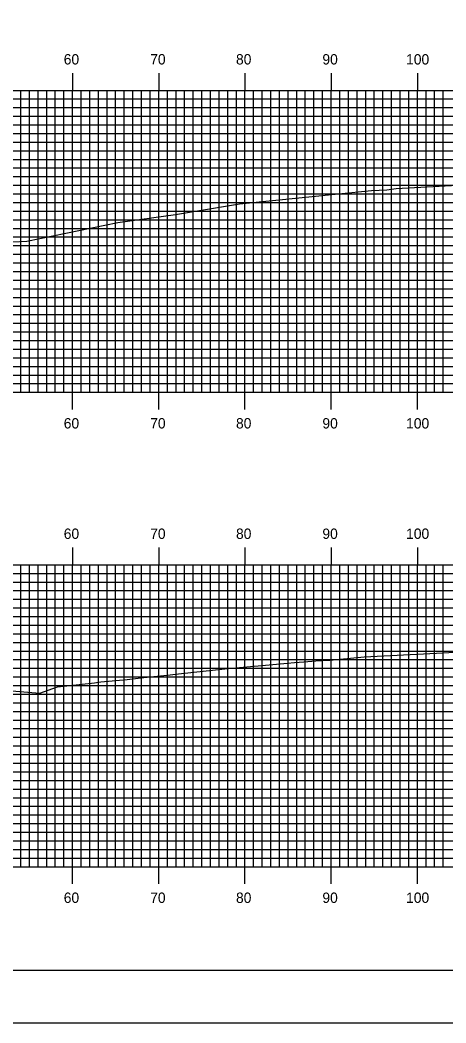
# Model space of a CAD drawing. Extents: x 851742 to 852085, y 364785 to 365005.
# Drawn here: x 851961.6 to 852011, y 364785.1 to 364901.4 of the extents above; entities that cross this region are included whole.
import ezdxf

# ---------------------------------------------------------------- set-up
doc = ezdxf.new("R2010")
doc.units = 0
for name, color, linetype in [('BORDER', 7, 'Continuous'), ('H_V ANNOTATION', 7, 'Continuous'), ('MAJOR', 7, 'Continuous'), ('MINOR', 7, 'Continuous'), ('PLOT BOUNDARY', 7, 'Continuous'), ('S_Roadway_Centerline', 7, 'Continuous')]:
    doc.layers.add(name, color=color, linetype=linetype)

msp = doc.modelspace()

# ---------------------------------------------------------------- linework, layer by layer
at = {"layer": 'BORDER'}
msp.add_lwpolyline([(851758.1, 364791.23), (852078.1, 364791.23), (852078.1, 365001.23), (851758.1, 365001.23)], close=True, dxfattribs=at)
at = {"layer": 'MAJOR'}
for p, q in [((851967.7, 364895.24), (851967.7, 364893.23)), ((851977.7, 364895.24), (851977.7, 364893.23)), ((851987.7, 364895.24), (851987.7, 364893.23)), ((851997.7, 364895.24), (851997.7, 364893.23)), ((852007.7, 364895.24), (852007.7, 364893.23)), ((851767.7, 364893.23), (852047.7, 364893.23)), ((851767.7, 364893.23), (852047.7, 364893.23)), ((851967.7, 364858.23), (851967.7, 364893.23)), ((851977.7, 364858.23), (851977.7, 364893.23)), ((851987.7, 364858.23), (851987.7, 364893.23)), ((851997.7, 364858.23), (851997.7, 364893.23)), ((852007.7, 364858.23), (852007.7, 364893.23)), ((851767.7, 364888.23), (852047.7, 364888.23)), ((851767.7, 364883.23), (852047.7, 364883.23)), ((851767.7, 364878.23), (852047.7, 364878.23)), ((851767.7, 364873.23), (852047.7, 364873.23)), ((851767.7, 364868.23), (852047.7, 364868.23)), ((851767.7, 364863.23), (852047.7, 364863.23)), ((851767.7, 364858.23), (852047.7, 364858.23)), ((851767.7, 364858.23), (852047.7, 364858.23)), ((851967.7, 364856.23), (851967.7, 364858.23)), ((851977.7, 364856.23), (851977.7, 364858.23)), ((851987.7, 364856.23), (851987.7, 364858.23)), ((851997.7, 364856.23), (851997.7, 364858.23)), ((852007.7, 364856.23), (852007.7, 364858.23)), ((851967.7, 364840.24), (851967.7, 364838.23)), ((851977.7, 364840.24), (851977.7, 364838.23)), ((851987.7, 364840.24), (851987.7, 364838.23)), ((851997.7, 364840.24), (851997.7, 364838.23)), ((852007.7, 364840.24), (852007.7, 364838.23)), ((851767.7, 364838.23), (852047.7, 364838.23)), ((851767.7, 364838.23), (852047.7, 364838.23)), ((851967.7, 364803.23), (851967.7, 364838.23)), ((851977.7, 364803.23), (851977.7, 364838.23)), ((851987.7, 364803.23), (851987.7, 364838.23)), ((851997.7, 364803.23), (851997.7, 364838.23)), ((852007.7, 364803.23), (852007.7, 364838.23)), ((851767.7, 364833.23), (852047.7, 364833.23)), ((851767.7, 364828.23), (852047.7, 364828.23)), ((851767.7, 364823.23), (852047.7, 364823.23)), ((851767.7, 364818.23), (852047.7, 364818.23)), ((851767.7, 364813.23), (852047.7, 364813.23)), ((851767.7, 364808.23), (852047.7, 364808.23)), ((851767.7, 364803.23), (852047.7, 364803.23)), ((851767.7, 364803.23), (852047.7, 364803.23)), ((851967.7, 364801.23), (851967.7, 364803.23)), ((851977.7, 364801.23), (851977.7, 364803.23)), ((851987.7, 364801.23), (851987.7, 364803.23)), ((851997.7, 364801.23), (851997.7, 364803.23)), ((852007.7, 364801.23), (852007.7, 364803.23))]:
    msp.add_line(p, q, dxfattribs=at)
at = {"layer": 'MINOR'}
for p, q in [((851961.7, 364858.23), (851961.7, 364893.23)), ((851962.7, 364858.23), (851962.7, 364893.23)), ((851963.7, 364858.23), (851963.7, 364893.23)), ((851964.7, 364858.23), (851964.7, 364893.23)), ((851965.7, 364858.23), (851965.7, 364893.23)), ((851966.7, 364858.23), (851966.7, 364893.23)), ((851968.7, 364858.23), (851968.7, 364893.23)), ((851969.7, 364858.23), (851969.7, 364893.23)), ((851970.7, 364858.23), (851970.7, 364893.23)), ((851971.7, 364858.23), (851971.7, 364893.23)), ((851972.7, 364858.23), (851972.7, 364893.23)), ((851973.7, 364858.23), (851973.7, 364893.23)), ((851974.7, 364858.23), (851974.7, 364893.23)), ((851975.7, 364858.23), (851975.7, 364893.23)), ((851976.7, 364858.23), (851976.7, 364893.23)), ((851978.7, 364858.23), (851978.7, 364893.23)), ((851979.7, 364858.23), (851979.7, 364893.23)), ((851980.7, 364858.23), (851980.7, 364893.23)), ((851981.7, 364858.23), (851981.7, 364893.23)), ((851982.7, 364858.23), (851982.7, 364893.23)), ((851983.7, 364858.23), (851983.7, 364893.23)), ((851984.7, 364858.23), (851984.7, 364893.23)), ((851985.7, 364858.23), (851985.7, 364893.23)), ((851986.7, 364858.23), (851986.7, 364893.23)), ((851988.7, 364858.23), (851988.7, 364893.23)), ((851989.7, 364858.23), (851989.7, 364893.23)), ((851990.7, 364858.23), (851990.7, 364893.23)), ((851991.7, 364858.23), (851991.7, 364893.23)), ((851992.7, 364858.23), (851992.7, 364893.23)), ((851993.7, 364858.23), (851993.7, 364893.23)), ((851994.7, 364858.23), (851994.7, 364893.23)), ((851995.7, 364858.23), (851995.7, 364893.23)), ((851996.7, 364858.23), (851996.7, 364893.23)), ((851998.7, 364858.23), (851998.7, 364893.23)), ((851999.7, 364858.23), (851999.7, 364893.23)), ((852000.7, 364858.23), (852000.7, 364893.23)), ((852001.7, 364858.23), (852001.7, 364893.23)), ((852002.7, 364858.23), (852002.7, 364893.23)), ((852003.7, 364858.23), (852003.7, 364893.23)), ((852004.7, 364858.23), (852004.7, 364893.23)), ((852005.7, 364858.23), (852005.7, 364893.23)), ((852006.7, 364858.23), (852006.7, 364893.23)), ((852008.7, 364858.23), (852008.7, 364893.23)), ((852009.7, 364858.23), (852009.7, 364893.23)), ((852010.7, 364858.23), (852010.7, 364893.23)), ((851767.7, 364892.23), (852047.7, 364892.23)), ((851767.7, 364891.23), (852047.7, 364891.23)), ((851767.7, 364890.23), (852047.7, 364890.23)), ((851767.7, 364889.23), (852047.7, 364889.23)), ((851767.7, 364887.23), (852047.7, 364887.23)), ((851767.7, 364886.23), (852047.7, 364886.23)), ((851767.7, 364885.23), (852047.7, 364885.23)), ((851767.7, 364884.23), (852047.7, 364884.23)), ((851767.7, 364882.23), (852047.7, 364882.23)), ((851767.7, 364881.23), (852047.7, 364881.23)), ((851767.7, 364880.23), (852047.7, 364880.23)), ((851767.7, 364879.23), (852047.7, 364879.23)), ((851767.7, 364877.23), (852047.7, 364877.23)), ((851767.7, 364876.23), (852047.7, 364876.23)), ((851767.7, 364875.23), (852047.7, 364875.23)), ((851767.7, 364874.23), (852047.7, 364874.23)), ((851767.7, 364872.23), (852047.7, 364872.23)), ((851767.7, 364871.23), (852047.7, 364871.23)), ((851767.7, 364870.23), (852047.7, 364870.23)), ((851767.7, 364869.23), (852047.7, 364869.23)), ((851767.7, 364867.23), (852047.7, 364867.23)), ((851767.7, 364866.23), (852047.7, 364866.23)), ((851767.7, 364865.23), (852047.7, 364865.23)), ((851767.7, 364864.23), (852047.7, 364864.23)), ((851767.7, 364862.23), (852047.7, 364862.23)), ((851767.7, 364861.23), (852047.7, 364861.23)), ((851767.7, 364860.23), (852047.7, 364860.23)), ((851767.7, 364859.23), (852047.7, 364859.23)), ((851961.7, 364803.23), (851961.7, 364838.23)), ((851962.7, 364803.23), (851962.7, 364838.23)), ((851963.7, 364803.23), (851963.7, 364838.23)), ((851964.7, 364803.23), (851964.7, 364838.23)), ((851965.7, 364803.23), (851965.7, 364838.23)), ((851966.7, 364803.23), (851966.7, 364838.23)), ((851968.7, 364803.23), (851968.7, 364838.23)), ((851969.7, 364803.23), (851969.7, 364838.23)), ((851970.7, 364803.23), (851970.7, 364838.23)), ((851971.7, 364803.23), (851971.7, 364838.23)), ((851972.7, 364803.23), (851972.7, 364838.23)), ((851973.7, 364803.23), (851973.7, 364838.23)), ((851974.7, 364803.23), (851974.7, 364838.23)), ((851975.7, 364803.23), (851975.7, 364838.23)), ((851976.7, 364803.23), (851976.7, 364838.23)), ((851978.7, 364803.23), (851978.7, 364838.23)), ((851979.7, 364803.23), (851979.7, 364838.23)), ((851980.7, 364803.23), (851980.7, 364838.23)), ((851981.7, 364803.23), (851981.7, 364838.23)), ((851982.7, 364803.23), (851982.7, 364838.23)), ((851983.7, 364803.23), (851983.7, 364838.23)), ((851984.7, 364803.23), (851984.7, 364838.23)), ((851985.7, 364803.23), (851985.7, 364838.23)), ((851986.7, 364803.23), (851986.7, 364838.23)), ((851988.7, 364803.23), (851988.7, 364838.23)), ((851989.7, 364803.23), (851989.7, 364838.23)), ((851990.7, 364803.23), (851990.7, 364838.23)), ((851991.7, 364803.23), (851991.7, 364838.23)), ((851992.7, 364803.23), (851992.7, 364838.23)), ((851993.7, 364803.23), (851993.7, 364838.23)), ((851994.7, 364803.23), (851994.7, 364838.23)), ((851995.7, 364803.23), (851995.7, 364838.23)), ((851996.7, 364803.23), (851996.7, 364838.23)), ((851998.7, 364803.23), (851998.7, 364838.23)), ((851999.7, 364803.23), (851999.7, 364838.23)), ((852000.7, 364803.23), (852000.7, 364838.23)), ((852001.7, 364803.23), (852001.7, 364838.23)), ((852002.7, 364803.23), (852002.7, 364838.23)), ((852003.7, 364803.23), (852003.7, 364838.23)), ((852004.7, 364803.23), (852004.7, 364838.23)), ((852005.7, 364803.23), (852005.7, 364838.23)), ((852006.7, 364803.23), (852006.7, 364838.23)), ((852008.7, 364803.23), (852008.7, 364838.23)), ((852009.7, 364803.23), (852009.7, 364838.23)), ((852010.7, 364803.23), (852010.7, 364838.23)), ((851767.7, 364837.23), (852047.7, 364837.23)), ((851767.7, 364836.23), (852047.7, 364836.23)), ((851767.7, 364835.23), (852047.7, 364835.23)), ((851767.7, 364834.23), (852047.7, 364834.23)), ((851767.7, 364832.23), (852047.7, 364832.23)), ((851767.7, 364831.23), (852047.7, 364831.23)), ((851767.7, 364830.23), (852047.7, 364830.23)), ((851767.7, 364829.23), (852047.7, 364829.23)), ((851767.7, 364827.23), (852047.7, 364827.23)), ((851767.7, 364826.23), (852047.7, 364826.23)), ((851767.7, 364825.23), (852047.7, 364825.23)), ((851767.7, 364824.23), (852047.7, 364824.23)), ((851767.7, 364822.23), (852047.7, 364822.23)), ((851767.7, 364821.23), (852047.7, 364821.23)), ((851767.7, 364820.23), (852047.7, 364820.23)), ((851767.7, 364819.23), (852047.7, 364819.23)), ((851767.7, 364817.23), (852047.7, 364817.23)), ((851767.7, 364816.23), (852047.7, 364816.23)), ((851767.7, 364815.23), (852047.7, 364815.23)), ((851767.7, 364814.23), (852047.7, 364814.23)), ((851767.7, 364812.23), (852047.7, 364812.23)), ((851767.7, 364811.23), (852047.7, 364811.23)), ((851767.7, 364810.23), (852047.7, 364810.23)), ((851767.7, 364809.23), (852047.7, 364809.23)), ((851767.7, 364807.23), (852047.7, 364807.23)), ((851767.7, 364806.23), (852047.7, 364806.23)), ((851767.7, 364805.23), (852047.7, 364805.23)), ((851767.7, 364804.23), (852047.7, 364804.23))]:
    msp.add_line(p, q, dxfattribs=at)
at = {"layer": 'PLOT BOUNDARY'}
msp.add_lwpolyline([(851741.92, 364785.11), (852081.92, 364785.11), (852081.92, 365005.11), (851741.92, 365005.11)], close=True, dxfattribs=at)
at = {"layer": 'S_Roadway_Centerline'}
for points in [[(851957.38, 364875.53), (851962.41, 364875.74), (851972.95, 364877.92), (851979.66, 364878.84), (851987.06, 364880.07), (852002.38, 364881.62), (852004.16, 364881.69), (852005.24, 364881.86), (852013.79, 364882.32), (852020.64, 364882.8), (852024.01, 364883.07), (852036.16, 364883.49), (852046.27, 364883.75), (852047.7, 364883.79)], [(851960.21, 364823.65), (851963.91, 364823.33), (851965.96, 364824.08), (851970.25, 364824.53), (851971, 364824.66), (851974.04, 364824.92), (851975.96, 364825.17), (851978.67, 364825.44), (851980.34, 364825.62), (851985.36, 364826.15), (851992.65, 364826.81), (851993.43, 364826.89), (851994.51, 364826.99), (851995.91, 364827.09), (851997.55, 364827.19), (852001.51, 364827.55), (852009.91, 364827.99), (852024.86, 364828.78)]]:
    msp.add_lwpolyline(points, dxfattribs=at)

# ---------------------------------------------------------------- texts
at = {"layer": 'H_V ANNOTATION'}
for s, p in [('60', (851966.68, 364896.23)), ('70', (851976.71, 364896.23)), ('80', (851986.66, 364896.23)), ('90', (851996.68, 364896.23)), ('100', (852006.39, 364896.23)), ('60', (851966.68, 364854.03)), ('70', (851976.71, 364854.03)), ('80', (851986.66, 364854.03)), ('90', (851996.68, 364854.03)), ('100', (852006.39, 364854.03)), ('60', (851966.68, 364841.23)), ('70', (851976.71, 364841.23)), ('80', (851986.66, 364841.23)), ('90', (851996.68, 364841.23)), ('100', (852006.39, 364841.23)), ('60', (851966.68, 364799.03)), ('70', (851976.71, 364799.03)), ('80', (851986.66, 364799.03)), ('90', (851996.68, 364799.03)), ('100', (852006.39, 364799.03))]:
    msp.add_text(s, height=1.2, dxfattribs=at).set_placement(p)

doc.saveas('drawing.dxf')
